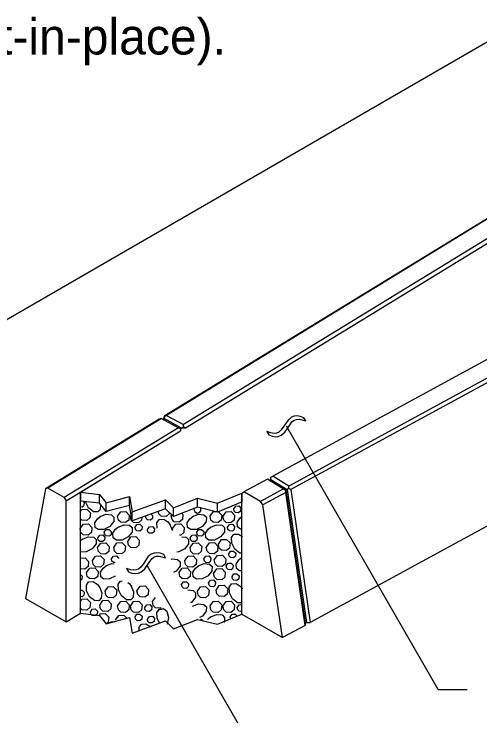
# Model space of a CAD drawing. Extents: x 99862 to 103151, y 100000 to 102076.
# Drawn here: x 102563.6 to 102822.9, y 100923.4 to 101314 of the extents above; entities that cross this region are included whole.
import ezdxf

# ---------------------------------------------------------------- set-up
doc = ezdxf.new("R2010")
doc.units = 0
for name, color, linetype in [('Level 15', 7, 'Continuous'), ('Level 2', 7, 'Continuous'), ('Level 20', 7, 'Continuous'), ('Level 25', 7, 'Continuous'), ('Level 41', 7, 'Continuous'), ('Level 7', 7, 'Continuous')]:
    doc.layers.add(name, color=color, linetype=linetype)

msp = doc.modelspace()

# ---------------------------------------------------------------- linework, layer by layer
at = {"layer": 'Level 15'}
for p, q in [((103034.94, 101418.41), (101857.32, 100738.42)), ((102799.73, 100938.18), (102715.2, 101084.58)), ((102715.75, 100871.77), (102637.65, 101007.04)), ((102799.73, 100938.18), (102815.73, 100938.18))]:
    msp.add_line(p, q, dxfattribs=at)
at = {"layer": 'Level 2'}
for p, q in [((102842.01, 101209.39), (102647.13, 101090.12)), ((102843.3, 101209.89), (102648.42, 101090.62)), ((102849.82, 101202.94), (102657.88, 101085.47)), ((102914.17, 101169.28), (102707.59, 101056.77)), ((102923.09, 101163.82), (102716.51, 101051.31)), ((102924.31, 101161.87), (102717.73, 101049.36)), ((102644.38, 101088.44), (102581.11, 101049.72)), ((102645.68, 101088.94), (102582.37, 101050.19)), ((102644.38, 101088.44), (102645.54, 101089)), ((102645.68, 101088.94), (102655.13, 101083.79)), ((102647.2, 101088.87), (102646.55, 101088.46)), ((102647.13, 101090.12), (102646.85, 101088.65)), ((102647.2, 101088.87), (102647.08, 101088.18)), ((102647.27, 101090.06), (102647.2, 101088.87)), ((102656.85, 101083.61), (102647.2, 101088.87)), ((102647.27, 101090.06), (102648.42, 101090.62)), ((102648.42, 101090.62), (102657.88, 101085.47)), ((102935.1, 101087.89), (102728.51, 100975.38)), ((102655.13, 101083.79), (102591.57, 101044.88)), ((102656.19, 101083.19), (102655.13, 101083.79)), ((102656.85, 101083.61), (102657.91, 101084.24)), ((102657.91, 101084.24), (102657.88, 101085.47)), ((102658.97, 101083.65), (102657.91, 101084.24)), ((102592.63, 101043.05), (102656.22, 101081.97)), ((102656.19, 101083.19), (102656.22, 101081.97)), ((102656.22, 101081.97), (102656.22, 101081.97)), ((102706.52, 101056.18), (102707.59, 101056.77)), ((102716.51, 101051.31), (102707.59, 101056.77)), ((102704.68, 101055.19), (102691.54, 101048.03)), ((102713.6, 101049.73), (102704.68, 101055.19)), ((102705.77, 101054.56), (102704.71, 101055.19)), ((102705.77, 101054.56), (102706.49, 101054.95)), ((102705.77, 101054.56), (102714.86, 101048.99)), ((102706.49, 101054.95), (102706.52, 101056.18)), ((102706.49, 101054.95), (102715.59, 101049.38)), ((102581.11, 101049.72), (102569.99, 100988.75)), ((102582.37, 101050.19), (102581.11, 101049.72)), ((102591.57, 101044.88), (102582.37, 101050.19)), ((102713.6, 101049.73), (102700.74, 101042.72)), ((102714.74, 101049.04), (102713.6, 101049.73)), ((102714.82, 101047.77), (102714.74, 101049.04)), ((102715.59, 101049.38), (102714.86, 101048.99)), ((102714.86, 101048.99), (102725.65, 100975.03)), ((102716.58, 101050.04), (102715.59, 101049.38)), ((102715.59, 101049.38), (102726.37, 100975.42)), ((102716.58, 101050.04), (102716.51, 101051.31)), ((102717.73, 101049.36), (102716.58, 101050.04)), ((102717.73, 101049.36), (102728.51, 100975.38)), ((102591.57, 101044.88), (102592.63, 101043.05)), ((102690.48, 101047.42), (102691.54, 101048.03)), ((102690.48, 100980.06), (102690.48, 101047.42)), ((102700.74, 101042.72), (102691.54, 101048.03)), ((102714.82, 101047.77), (102702, 101040.79)), ((102725.6, 100973.79), (102714.82, 101047.77)), ((102592.63, 100975.68), (102592.63, 101043.05)), ((102702, 101040.79), (102700.74, 101042.72)), ((102713.11, 100966.99), (102702, 101040.79)), ((102569.99, 100988.75), (102592.63, 100975.68)), ((102592.63, 100975.68), (102600.52, 100980.51)), ((102690.48, 100980.06), (102713.11, 100966.99)), ((102725.65, 100975.03), (102725.6, 100973.79)), ((102726.37, 100975.42), (102725.65, 100975.03)), ((102726.37, 100975.42), (102728.51, 100975.38)), ((102725.6, 100973.79), (102713.11, 100966.99))]:
    msp.add_line(p, q, dxfattribs=at)
at = {"layer": 'Level 20'}
for p, q in [((102716.11, 101088.01), (102713.84, 101084.6)), ((102718.04, 101089.55), (102716.11, 101088.01)), ((102719.57, 101090.2), (102718.04, 101089.55)), ((102718.28, 101086.97), (102719.44, 101087.92)), ((102719.44, 101087.92), (102720.78, 101088.4)), ((102721.17, 101090.37), (102719.57, 101090.2)), ((102720.78, 101088.4), (102722.43, 101088.46)), ((102722.93, 101090.1), (102721.17, 101090.37)), ((102722.43, 101088.46), (102726, 101087.53)), ((102724.94, 101089.36), (102722.93, 101090.1)), ((102726, 101087.53), (102724.94, 101089.36)), ((102713.84, 101084.6), (102712.38, 101082.52)), ((102714.37, 101081.36), (102716.9, 101084.98)), ((102716.9, 101084.98), (102718.28, 101086.97)), ((102704.31, 101081.63), (102705.37, 101079.79)), ((102706.62, 101080.89), (102704.31, 101081.62)), ((102708.33, 101080.62), (102706.62, 101080.89)), ((102709.69, 101080.76), (102708.33, 101080.62)), ((102710.92, 101081.26), (102709.69, 101080.76)), ((102712.38, 101082.52), (102710.92, 101081.26)), ((102712.29, 101079.61), (102714.37, 101081.36)), ((102705.37, 101079.79), (102707.2, 101079.03)), ((102707.2, 101079.03), (102708.97, 101078.74)), ((102708.97, 101078.74), (102710.66, 101078.93)), ((102710.66, 101078.93), (102712.29, 101079.61)), ((102641.53, 101014.04), (102640, 101013.39)), ((102643.14, 101014.22), (102641.53, 101014.04)), ((102644.9, 101013.95), (102643.14, 101014.22)), ((102646.91, 101013.2), (102644.9, 101013.95)), ((102638.08, 101011.85), (102635.81, 101008.45)), ((102640, 101013.39), (102638.08, 101011.85)), ((102638.86, 101008.82), (102640.25, 101010.81)), ((102640.25, 101010.81), (102641.41, 101011.76)), ((102641.41, 101011.76), (102642.75, 101012.24)), ((102642.75, 101012.24), (102644.39, 101012.3)), ((102644.39, 101012.3), (102647.97, 101011.37)), ((102647.97, 101011.37), (102646.91, 101013.2)), ((102634.34, 101006.36), (102632.89, 101005.11)), ((102635.81, 101008.45), (102634.34, 101006.36)), ((102636.34, 101005.2), (102638.86, 101008.82)), ((102628.59, 101004.73), (102626.28, 101005.47)), ((102626.28, 101005.47), (102627.33, 101003.64)), ((102627.33, 101003.64), (102629.17, 101002.87)), ((102630.3, 101004.46), (102628.59, 101004.73)), ((102629.17, 101002.87), (102630.94, 101002.58)), ((102631.65, 101004.61), (102630.3, 101004.46)), ((102630.94, 101002.58), (102632.63, 101002.78)), ((102632.89, 101005.11), (102631.65, 101004.61)), ((102632.63, 101002.78), (102634.26, 101003.45)), ((102634.26, 101003.45), (102636.34, 101005.2))]:
    msp.add_line(p, q, dxfattribs=at)
at = {"layer": 'Level 25'}
for p, q in [((102658.97, 101083.65), (102849.82, 101200.45)), ((102600.52, 101047.88), (102656.22, 101081.97)), ((102656.85, 101083.61), (102656.18, 101083.2)), ((102656.22, 101081.97), (102656.22, 101081.97)), ((102656.85, 101083.61), (102658.97, 101083.65)), ((102706.49, 101054.11), (102706.49, 101054.95)), ((102600.52, 101047.88), (102600.52, 101042.98)), ((102600.52, 100980.51), (102600.52, 101047.88))]:
    msp.add_line(p, q, dxfattribs=at)
at = {"layer": 'Level 41'}
for p, q in [((102611.12, 101041.78), (102611.12, 101046.68)), ((102627.95, 101040.55), (102627.95, 101045.45)), ((102690.49, 101042.52), (102690.49, 101047.42)), ((102611.12, 101041.78), (102600.52, 101042.98)), ((102614.89, 101037.06), (102611.12, 101041.78)), ((102614.89, 101037.06), (102614.89, 101041.96)), ((102647.94, 101038.72), (102647.94, 101043.62)), ((102665.77, 101039.58), (102665.77, 101044.48)), ((102690.49, 101042.52), (102676.76, 101036.86)), ((102676.76, 101036.86), (102676.76, 101041.75)), ((102627.95, 101040.55), (102614.89, 101037.06)), ((102629.35, 101031.98), (102627.95, 101040.55)), ((102647.94, 101038.72), (102629.35, 101031.98)), ((102629.35, 101031.98), (102629.35, 101036.88)), ((102652.27, 101034.33), (102647.94, 101038.72)), ((102665.77, 101039.58), (102652.27, 101034.33)), ((102652.27, 101034.33), (102652.27, 101039.23)), ((102676.76, 101036.86), (102665.77, 101039.58))]:
    msp.add_line(p, q, dxfattribs=at)
for points in [[(102600.52, 101047.88), (102611.12, 101046.68), (102614.89, 101041.96), (102627.95, 101045.45), (102629.35, 101036.88), (102647.94, 101043.62), (102652.27, 101039.23), (102665.77, 101044.48), (102676.76, 101041.75), (102690.48, 101047.42)], [(102600.52, 100980.51), (102611.12, 100979.32), (102614.89, 100974.6), (102627.95, 100978.08), (102629.35, 100969.52), (102647.95, 100976.25), (102652.27, 100971.86), (102665.77, 100977.12), (102676.77, 100974.39), (102690.48, 100980.06)]]:
    msp.add_lwpolyline(points, dxfattribs=at)
at = {"layer": 'Level 7'}
for points in [[(102601.82, 101043.04), (102602.65, 101042.18), (102602.48, 101040.49), (102601.45, 101039.63), (102600.43, 101039.71)], [(102611.74, 101040.79), (102611.53, 101038.32), (102610.17, 101036.89), (102607.74, 101036.94), (102604.97, 101039.1), (102603.29, 101042.45)], [(102600.44, 101036.91), (102601.4, 101038.28), (102604.2, 101038.44), (102606.14, 101036.43), (102605.85, 101033.61), (102604.13, 101032.18), (102601.37, 101032.38), (102600.44, 101033.28)], [(102621.24, 101034.56), (102622.99, 101037.05), (102625.78, 101037.21), (102627.72, 101035.2), (102627.44, 101032.38), (102625.72, 101030.94), (102622.96, 101031.14), (102621.67, 101032.4), (102621.25, 101034.56)], [(102650.01, 101036.74), (102649.92, 101035.8), (102648.19, 101034.37), (102645.44, 101034.57), (102644.14, 101035.83), (102643.93, 101036.91)], [(102663.79, 101038.81), (102663.75, 101038.76), (102664.02, 101037.11), (102665.61, 101036.22)], [(102665.61, 101036.22), (102666.87, 101036.61), (102667.54, 101037.46), (102667.49, 101039.12), (102667.41, 101039.2)], [(102672.69, 101034.56), (102674.44, 101037.05), (102677.23, 101037.21), (102679.17, 101035.2), (102678.89, 101032.38), (102677.16, 101030.94), (102674.41, 101031.14), (102673.11, 101032.4), (102672.69, 101034.56)], [(102679.88, 101034.46), (102681.63, 101036.94), (102684.42, 101037.1), (102686.36, 101035.09), (102686.08, 101032.27), (102684.36, 101030.84), (102681.6, 101031.04), (102680.3, 101032.3), (102679.88, 101034.46)], [(102685.93, 101038.66), (102686.98, 101040.15), (102688.65, 101040.25), (102689.81, 101039.04), (102689.65, 101037.35), (102688.61, 101036.49), (102686.96, 101036.61), (102686.18, 101037.36), (102685.93, 101038.66)], [(102611.49, 101034.34), (102614.76, 101035.63), (102617.77, 101035.37), (102619.2, 101034.01), (102619.15, 101031.58), (102616.98, 101028.81), (102613.63, 101027.13), (102610.48, 101027.08), (102608.7, 101028.34), (102608.53, 101030.85), (102609.98, 101033.1), (102611.63, 101034.42)], [(102628.43, 101034.46), (102628.89, 101035.1)], [(102634.79, 101033.85), (102634.63, 101032.27), (102632.91, 101030.84), (102630.15, 101031.04), (102628.86, 101032.3), (102628.44, 101034.46)], [(102639.97, 101035.76), (102640.74, 101034.96), (102640.58, 101033.26), (102639.54, 101032.4), (102637.89, 101032.52), (102637.11, 101033.28), (102636.86, 101034.57)], [(102636.86, 101034.58), (102637, 101034.77)], [(102656.84, 101036.22), (102657.58, 101035.46), (102657.3, 101032.64), (102655.58, 101031.2), (102652.82, 101031.4), (102651.53, 101032.66), (102651.1, 101034.82)], [(102651.1, 101034.82), (102651.49, 101035.37)], [(102662.94, 101034.34), (102666.21, 101035.63), (102669.21, 101035.37), (102670.64, 101034.01), (102670.6, 101031.58), (102668.43, 101028.81), (102665.08, 101027.13), (102661.93, 101027.08), (102660.15, 101028.34), (102659.98, 101030.85), (102661.42, 101033.1), (102663.07, 101034.42)], [(102690.6, 101027.36), (102689.71, 101027.34), (102687.93, 101028.61), (102687.76, 101031.12), (102689.2, 101033.37), (102690.6, 101034.48)], [(102600.45, 101027.64), (102602.18, 101030.1), (102604.97, 101030.26), (102606.91, 101028.25), (102606.63, 101025.43), (102604.91, 101024), (102602.15, 101024.2), (102600.86, 101025.45), (102600.45, 101027.53)], [(102621.64, 101028.49), (102624.91, 101029.79), (102627.91, 101029.53), (102629.34, 101028.17), (102629.29, 101025.74), (102627.13, 101022.97), (102623.78, 101021.29), (102620.62, 101021.24), (102618.85, 101022.5), (102618.68, 101025.01), (102620.12, 101027.26), (102621.77, 101028.58)], [(102630.98, 101028.44), (102632.03, 101029.94), (102633.7, 101030.03), (102634.86, 101028.82), (102634.7, 101027.13), (102633.66, 101026.27), (102632.01, 101026.39), (102631.23, 101027.15), (102630.98, 101028.44)], [(102643.19, 101027.81), (102643.14, 101030.93), (102644.4, 101032.71), (102646.91, 101032.88), (102649.16, 101031.43), (102650.48, 101029.78)], [(102650.39, 101029.92), (102651.63, 101026.79)], [(102651.88, 101027.61), (102653.63, 101030.1), (102656.42, 101030.26), (102658.36, 101028.25), (102658.08, 101025.43), (102656.35, 101024), (102655.77, 101024.04)], [(102673.09, 101028.49), (102676.36, 101029.79), (102679.36, 101029.53), (102680.79, 101028.17), (102680.74, 101025.74), (102678.57, 101022.97), (102675.23, 101021.29), (102672.07, 101021.24), (102670.29, 101022.5), (102670.13, 101025.01), (102671.57, 101027.26), (102673.22, 101028.58)], [(102682.42, 101028.44), (102683.47, 101029.94), (102685.15, 101030.03), (102686.31, 101028.82), (102686.14, 101027.13), (102685.11, 101026.27), (102683.46, 101026.39), (102682.68, 101027.15), (102682.43, 101028.44)], [(102613.85, 101025.57), (102614.9, 101027.07), (102616.57, 101027.16), (102617.73, 101025.96), (102617.57, 101024.26), (102616.53, 101023.4), (102614.88, 101023.52), (102614.1, 101024.28), (102613.85, 101025.57)], [(102637.86, 101027.21), (102638.91, 101028.71), (102640.59, 101028.8), (102641.75, 101027.59), (102641.58, 101025.9), (102640.55, 101025.04), (102638.89, 101025.16), (102638.12, 101025.92), (102637.86, 101027.21)], [(102637.86, 101027.21), (102638.91, 101028.71), (102640.59, 101028.8), (102641.75, 101027.59), (102641.74, 101027.51)], [(102638.08, 101026.11), (102637.86, 101027.21)], [(102652.07, 101026.63), (102651.88, 101027.61)], [(102665.29, 101025.57), (102666.34, 101027.07), (102668.02, 101027.16), (102669.18, 101025.96), (102669.01, 101024.26), (102667.98, 101023.4), (102666.32, 101023.52), (102665.55, 101024.28), (102665.29, 101025.57)], [(102600.46, 101020.86), (102601.79, 101021.92)], [(102601.66, 101021.83), (102604.93, 101023.13), (102607.93, 101022.87), (102609.36, 101021.51), (102609.31, 101019.08), (102607.15, 101016.31), (102603.8, 101014.63), (102600.64, 101014.58), (102600.47, 101014.7)], [(102610.24, 101022.54), (102611.29, 101024.03), (102612.96, 101024.13), (102614.13, 101022.92), (102613.96, 101021.23), (102612.93, 101020.37), (102611.27, 101020.49), (102610.49, 101021.24), (102610.24, 101022.54)], [(102626.85, 101020.53), (102628.6, 101023.01), (102631.39, 101023.17), (102633.33, 101021.16), (102633.05, 101018.34), (102631.33, 101016.91), (102628.57, 101017.11), (102627.27, 101018.36), (102626.85, 101020.53)], [(102656.91, 101023.08), (102659.38, 101022.87), (102660.8, 101021.51), (102660.76, 101019.08), (102658.59, 101016.31), (102655.24, 101014.63), (102654.19, 101014.61)], [(102661.69, 101022.54), (102662.74, 101024.03), (102664.41, 101024.13), (102665.57, 101022.92), (102665.41, 101021.23), (102664.37, 101020.37), (102662.72, 101020.49), (102661.94, 101021.24), (102661.69, 101022.54)], [(102677.37, 101019), (102679.12, 101021.49), (102681.91, 101021.65), (102683.85, 101019.64), (102683.57, 101016.82), (102681.84, 101015.39), (102679.09, 101015.59), (102677.79, 101016.84), (102677.37, 101019)], [(102690.41, 101013.99), (102689.19, 101014.01), (102686.42, 101016.18), (102684.75, 101019.53), (102684.69, 101022.68), (102685.96, 101024.46), (102688.47, 101024.63), (102690.72, 101023.19)], [(102610.12, 101017.08), (102611.87, 101019.56), (102614.66, 101019.72), (102616.6, 101017.71), (102616.32, 101014.89), (102614.6, 101013.46), (102611.84, 101013.66), (102610.55, 101014.92), (102610.13, 101017.08)], [(102619.14, 101017.18), (102620.89, 101019.67), (102623.68, 101019.83), (102625.62, 101017.81), (102625.34, 101015), (102623.62, 101013.56), (102620.86, 101013.76), (102619.56, 101015.02), (102619.14, 101017.18)], [(102661.57, 101017.08), (102663.32, 101019.56), (102666.11, 101019.72), (102668.05, 101017.71), (102667.77, 101014.89), (102666.05, 101013.46), (102663.29, 101013.66), (102661.99, 101014.92), (102661.57, 101017.08)], [(102670.59, 101017.18), (102672.34, 101019.67), (102675.13, 101019.83), (102677.07, 101017.81), (102676.79, 101015), (102675.06, 101013.56), (102672.31, 101013.76), (102671.01, 101015.02), (102670.59, 101017.18)], [(102683.11, 101013.55), (102684.16, 101015.04), (102685.83, 101015.14), (102686.99, 101013.93), (102686.83, 101012.24), (102685.79, 101011.38), (102684.14, 101011.5), (102683.36, 101012.25), (102683.11, 101013.55)], [(102600.48, 101011.15), (102603.14, 101011.3), (102605.08, 101009.29), (102604.8, 101006.47), (102603.07, 101005.04), (102600.48, 101005.22)], [(102607.26, 101009.8), (102609.01, 101012.28), (102611.8, 101012.44), (102613.74, 101010.43), (102613.46, 101007.61), (102611.73, 101006.18), (102608.98, 101006.38), (102607.68, 101007.64), (102607.26, 101009.8)], [(102617.86, 101010.82), (102618.91, 101012.31), (102620.59, 101012.41), (102621.75, 101011.2), (102621.73, 101010.94)], [(102619.91, 101008.69), (102618.89, 101008.77), (102618.12, 101009.52), (102617.86, 101010.82)], [(102651.11, 101010.57), (102651.62, 101010.77), (102654.62, 101010.52), (102656.05, 101009.16), (102656, 101006.72), (102653.84, 101003.95), (102652.31, 101003.19)], [(102658.7, 101009.8), (102660.45, 101012.28), (102663.24, 101012.44), (102665.18, 101010.43), (102664.9, 101007.61), (102663.18, 101006.18), (102660.42, 101006.38), (102659.13, 101007.64), (102658.71, 101009.8)], [(102669.31, 101010.82), (102670.36, 101012.31), (102672.03, 101012.41), (102673.2, 101011.2), (102673.03, 101009.51), (102671.99, 101008.65), (102670.34, 101008.77), (102669.56, 101009.52), (102669.31, 101010.82)], [(102675.04, 101010.17), (102676.79, 101012.66), (102679.58, 101012.82), (102681.52, 101010.81), (102681.24, 101007.99), (102679.51, 101006.56), (102676.76, 101006.76), (102675.46, 101008.01), (102675.04, 101010.17)], [(102690.05, 101004.17), (102689.16, 101004.16), (102687.38, 101005.42), (102687.21, 101007.93), (102688.65, 101010.18), (102690.05, 101011.29)], [(102603.97, 101003.22), (102605.72, 101005.71), (102608.51, 101005.87), (102610.45, 101003.85), (102610.17, 101001.03), (102608.44, 100999.6), (102605.69, 100999.8), (102604.39, 101001.06), (102603.97, 101003.22)], [(102619.87, 101001.17), (102616.81, 100999.63), (102613.65, 100999.58), (102611.87, 101000.84), (102611.71, 101003.35), (102613.15, 101005.6), (102614.8, 101006.92)], [(102614.67, 101006.84), (102617.94, 101008.13), (102619.36, 101008.01)], [(102655.42, 101003.22), (102657.16, 101005.71), (102659.95, 101005.87), (102661.89, 101003.85), (102661.61, 101001.03), (102659.89, 100999.6), (102657.13, 100999.8), (102655.84, 101001.06), (102655.42, 101003.22)], [(102666.11, 101006.84), (102669.38, 101008.13), (102672.39, 101007.87), (102673.81, 101006.51), (102673.77, 101004.08), (102671.6, 101001.31), (102668.25, 100999.63), (102665.1, 100999.58), (102663.32, 101000.84), (102663.15, 101003.35), (102664.59, 101005.6), (102666.24, 101006.92)], [(102681.71, 101006.88), (102682.76, 101008.38), (102684.43, 101008.47), (102685.6, 101007.26), (102685.43, 101005.57), (102684.4, 101004.71), (102682.74, 101004.83), (102681.96, 101005.59), (102681.71, 101006.88)], [(102600.77, 101001.91), (102601.5, 101001.15), (102601.33, 100999.46), (102600.77, 100998.99)], [(102674.7, 101002.73), (102676.45, 101005.22), (102679.24, 101005.38), (102681.18, 101003.37), (102680.9, 101000.55), (102679.18, 100999.11), (102676.42, 100999.31), (102675.13, 101000.57), (102674.7, 101002.73)], [(102684.97, 101000.94), (102686.02, 101002.43), (102687.7, 101002.53), (102688.86, 101001.32), (102688.69, 100999.63), (102687.66, 100998.77), (102686.01, 100998.89), (102685.23, 100999.64), (102684.98, 101000.94)], [(102611.11, 100995.22), (102612.41, 100991.96), (102612.15, 100988.95), (102610.79, 100987.52), (102608.35, 100987.57), (102605.58, 100989.74), (102603.91, 100993.08), (102603.85, 100996.24), (102605.11, 100998.02), (102607.63, 100998.18), (102609.88, 100996.74), (102611.19, 100995.09)], [(102628.87, 100995.65), (102630.17, 100992.38), (102629.91, 100989.37), (102628.55, 100987.95), (102626.12, 100987.99), (102623.35, 100990.16), (102621.67, 100993.51), (102621.62, 100996.66), (102622.88, 100998.44), (102623.86, 100998.51)], [(102656.89, 100996.48), (102657.94, 100997.97), (102659.62, 100998.07), (102660.78, 100996.86), (102660.61, 100995.17), (102659.58, 100994.31), (102657.92, 100994.43), (102657.15, 100995.18), (102656.89, 100996.48)], [(102671.89, 100997.47), (102672.94, 100998.96), (102674.61, 100999.06), (102675.78, 100997.85), (102675.61, 100996.16), (102674.57, 100995.3), (102672.92, 100995.42), (102672.14, 100996.18), (102671.89, 100997.47)], [(102614.25, 100992.75), (102616, 100995.24), (102618.79, 100995.4), (102620.73, 100993.39), (102620.45, 100990.57), (102618.72, 100989.13), (102615.97, 100989.33), (102614.67, 100990.59), (102614.25, 100992.75)], [(102626.87, 100997.66), (102627.64, 100997.17), (102628.96, 100995.52)], [(102632.02, 100993.06), (102633.76, 100995.55), (102636.55, 100995.7), (102638.49, 100993.69), (102638.21, 100990.87), (102636.49, 100989.44), (102633.73, 100989.64), (102632.44, 100990.9), (102632.02, 100993.06)], [(102665.7, 100992.75), (102667.44, 100995.24), (102670.23, 100995.4), (102672.17, 100993.39), (102671.89, 100990.57), (102670.17, 100989.13), (102667.41, 100989.33), (102666.12, 100990.59), (102665.7, 100992.75)], [(102676.06, 100993.42), (102677.8, 100995.91), (102680.6, 100996.07), (102682.54, 100994.06), (102682.25, 100991.24), (102680.53, 100989.81), (102677.77, 100990), (102676.48, 100991.26), (102676.06, 100993.42)], [(102690.58, 100986.59), (102690.36, 100986.36), (102687.93, 100986.41), (102685.16, 100988.57), (102683.48, 100991.92), (102683.43, 100995.08), (102684.69, 100996.85), (102687.2, 100997.02), (102689.45, 100995.58), (102690.51, 100994.26)], [(102690.51, 100994.26), (102690.56, 100994.19)], [(102600.5, 100993.42), (102601.49, 100993.47), (102602.65, 100992.27), (102602.48, 100990.58), (102601.45, 100989.71), (102600.51, 100989.78)], [(102660.42, 100993.53), (102663.26, 100993.28), (102664.69, 100991.92), (102664.65, 100989.49), (102662.48, 100986.72), (102661.77, 100986.36)], [(102600.51, 100987.09), (102601.4, 100988.36), (102604.2, 100988.52), (102606.14, 100986.51), (102605.85, 100983.69), (102604.13, 100982.26), (102601.37, 100982.46), (102600.52, 100983.29)], [(102611.27, 100985.11), (102613.01, 100987.6), (102615.8, 100987.76), (102617.74, 100985.75), (102617.46, 100982.93), (102615.74, 100981.49), (102612.98, 100981.69), (102611.69, 100982.95), (102611.27, 100985.11)], [(102621.24, 100984.65), (102622.99, 100987.13), (102625.78, 100987.29), (102627.72, 100985.28), (102627.44, 100982.46), (102625.72, 100981.03), (102622.96, 100981.23), (102621.67, 100982.48), (102621.25, 100984.64)], [(102628.43, 100984.54), (102630.18, 100987.03), (102632.97, 100987.19), (102634.91, 100985.17), (102634.63, 100982.36), (102632.91, 100980.92), (102630.15, 100981.12), (102628.86, 100982.38), (102628.44, 100984.54)], [(102640.62, 100987.01), (102642.27, 100989.37)], [(102645.52, 100983.75), (102645.09, 100983.39), (102642.33, 100983.59), (102641.04, 100984.85), (102640.62, 100987.01)], [(102672.69, 100984.65), (102674.44, 100987.13), (102677.23, 100987.29), (102679.17, 100985.28), (102678.89, 100982.46), (102677.16, 100981.03), (102674.41, 100981.23), (102673.11, 100982.48), (102672.69, 100984.64)], [(102679.88, 100984.54), (102681.63, 100987.03), (102684.42, 100987.19), (102686.36, 100985.17), (102686.08, 100982.36), (102684.36, 100980.92), (102681.6, 100981.12), (102680.3, 100982.38), (102679.88, 100984.54)], [(102606.11, 100981.37), (102607.16, 100982.86), (102608.83, 100982.96), (102610, 100981.75), (102609.83, 100980.06), (102608.8, 100979.2), (102607.14, 100979.32), (102606.36, 100980.07), (102606.11, 100981.37)], [(102636.39, 100983.77), (102637.44, 100985.26), (102639.11, 100985.36), (102640.27, 100984.15), (102640.11, 100982.46), (102639.07, 100981.6), (102637.42, 100981.72), (102636.64, 100982.47), (102636.39, 100983.77)], [(102644.78, 100974.67), (102643.19, 100977.86), (102643.14, 100981.01), (102644.4, 100982.79), (102646.01, 100982.9)], [(102643.17, 100980.97), (102644.83, 100982.81), (102646.77, 100983.13), (102648.69, 100981.62), (102649.59, 100978.22), (102648.9, 100974.54)], [(102662.94, 100984.42), (102666.21, 100985.71), (102669.21, 100985.45), (102670.64, 100984.1), (102670.6, 100981.66), (102668.43, 100978.89), (102666.8, 100978.08)], [(102687.83, 100983.77), (102688.88, 100985.26), (102690.56, 100985.36)], [(102690.52, 100981.6), (102688.87, 100981.72), (102688.09, 100982.47), (102687.84, 100983.77)], [(102611.14, 100979.59), (102611.55, 100980.18), (102614.34, 100980.34), (102616.28, 100978.33), (102616, 100975.51), (102615.04, 100974.72)], [(102620.15, 100976.82), (102621.9, 100979.31), (102624.69, 100979.47), (102626.3, 100977.8)], [(102621.03, 100978.07), (102621.77, 100978.66)], [(102630.98, 100978.53), (102632.03, 100980.02), (102633.7, 100980.11), (102634.86, 100978.91), (102634.7, 100977.22), (102633.66, 100976.35), (102632.01, 100976.47), (102631.23, 100977.23), (102630.98, 100978.53)], [(102637.86, 100977.3), (102638.91, 100978.79), (102640.59, 100978.88), (102641.75, 100977.68), (102641.58, 100975.99), (102640.55, 100975.13), (102638.89, 100975.25), (102638.12, 100976), (102637.86, 100977.3)], [(102671.34, 100977), (102671.57, 100977.34), (102673.22, 100978.66)], [(102673.09, 100978.58), (102676.36, 100979.87), (102679.36, 100979.61), (102680.79, 100978.26), (102680.74, 100975.82), (102680.39, 100975.37)], [(102683.99, 100978.53), (102685.04, 100980.02), (102686.72, 100980.11), (102687.88, 100978.91)], [(102684.22, 100977.34), (102683.99, 100978.53)], [(102614.89, 100974.6), (102618.16, 100975.9), (102619.52, 100975.78)], [(102633.29, 100970.51), (102633.25, 100972.77), (102634.51, 100974.54), (102637.02, 100974.71), (102639.27, 100973.27), (102639.64, 100972.81)], [(102667.31, 100977.2), (102668.02, 100977.24), (102669.1, 100976.12)]]:
    msp.add_lwpolyline(points, dxfattribs=at)

# ---------------------------------------------------------------- texts
at = {"layer": 'Level 20'}
msp.add_text('(cast-in-place).', height=20, dxfattribs=at).set_placement((102504.72, 101291.44))

doc.saveas('drawing.dxf')
